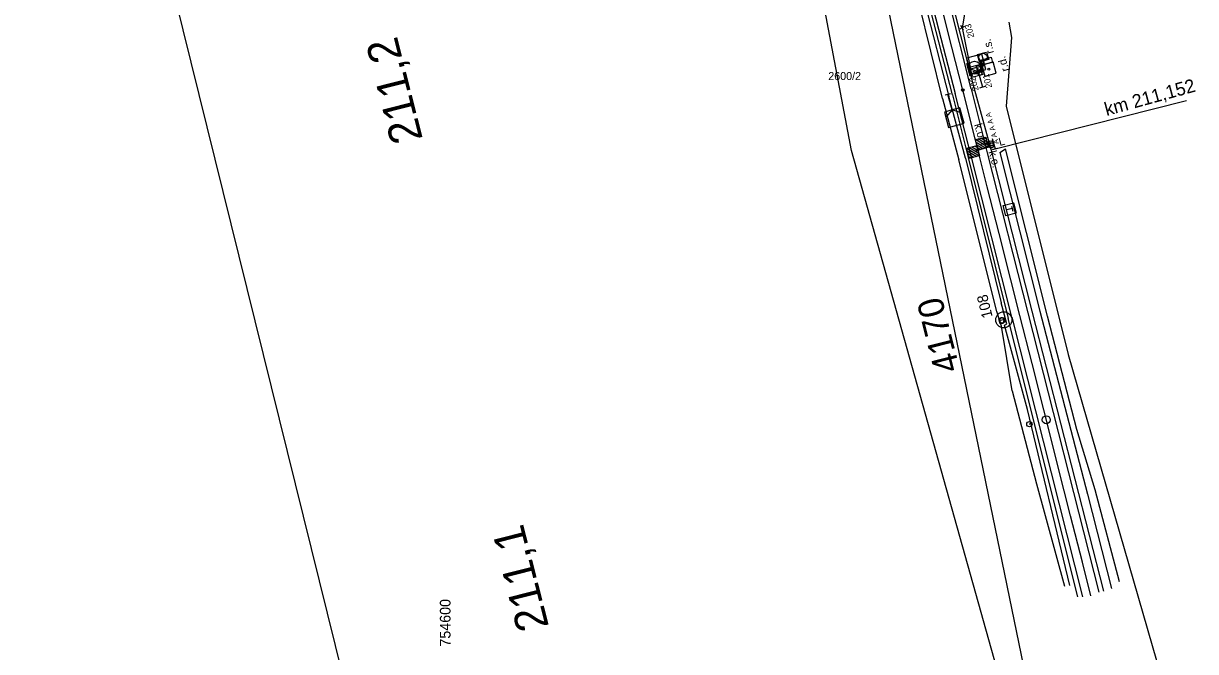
# Model space of a CAD drawing. Extents: x -754679 to -754173, y -1169241 to -1168288.
# Drawn here: x -754679.1 to -754459.3, y -1168596.9 to -1168479.1 of the extents above; entities that cross this region are included whole.
import ezdxf

# ---------------------------------------------------------------- set-up
doc = ezdxf.new("R2010")
doc.units = 0
for name, color, linetype in [('Default', 7, 'Continuous'), ('Vrstva 1', 7, 'Continuous'), ('Vrstva 11', 7, 'Continuous'), ('Vrstva 12', 7, 'Continuous'), ('Vrstva 16', 7, 'Continuous'), ('Vrstva 2', 7, 'Continuous'), ('Vrstva 23', 7, 'Continuous'), ('Vrstva 25', 7, 'Continuous'), ('Vrstva 27', 7, 'Continuous'), ('Vrstva 3', 7, 'Continuous'), ('Vrstva 33', 7, 'Continuous'), ('Vrstva 36', 7, 'Continuous'), ('Vrstva 4', 7, 'Continuous'), ('Vrstva 45', 7, 'Continuous'), ('Vrstva 53', 7, 'Continuous'), ('Vrstva 55', 7, 'Continuous'), ('Vrstva 57', 7, 'Continuous'), ('Vrstva 59', 7, 'Continuous'), ('Vrstva 6', 7, 'Continuous'), ('Vrstva 60', 7, 'Continuous'), ('Vrstva 61', 7, 'Continuous'), ('Vrstva 63', 7, 'Continuous'), ('Vrstva 7', 7, 'Continuous')]:
    doc.layers.add(name, color=color, linetype=linetype)

msp = doc.modelspace()

# ---------------------------------------------------------------- linework, layer by layer
at = {"layer": 'Vrstva 1'}
msp.add_line((-754495.29, -1168534.73), (-754495.29, -1168534.73), dxfattribs=at)
for points in [[(-754498.39, -1168509.75), (-754500.09, -1168503), (-754500.37, -1168501.89), (-754500.59, -1168501.05), (-754502.8, -1168492.33), (-754502.98, -1168491.62), (-754505.01, -1168483.59), (-754507.47, -1168473.86), (-754508.58, -1168469.47), (-754510.81, -1168460.63), (-754513.14, -1168451.47)], [(-754478.97, -1168586.46), (-754480.56, -1168580.17), (-754482.76, -1168571.47), (-754485.13, -1168562.12), (-754486.61, -1168556.26), (-754487.79, -1168551.61), (-754490, -1168542.89), (-754492.27, -1168533.93), (-754493.96, -1168527.25), (-754496.18, -1168518.51), (-754498.39, -1168509.75)]]:
    msp.add_lwpolyline(points, dxfattribs=at)
msp.add_circle((-754502.98, -1168491.62), 0.25, dxfattribs=at)
at = {"layer": 'Vrstva 11'}
for p, q in [((-754496.27, -1168534.44), (-754496.03, -1168535.41)), ((-754495.18, -1168534.68), (-754496.15, -1168534.92)), ((-754495.3, -1168534.19), (-754495.06, -1168535.16))]:
    msp.add_line(p, q, dxfattribs=at)
at = {"layer": 'Vrstva 12'}
for p, q in [((-754496.12, -1168534.91), (-754496.17, -1168534.91)), ((-754495.81, -1168534.34), (-754495.8, -1168534.38)), ((-754495.5, -1168535.26), (-754495.53, -1168535.37)), ((-754495.23, -1168534.71), (-754495.16, -1168534.7))]:
    msp.add_line(p, q, dxfattribs=at)
for centre, major_axis, ratio, start_param, end_param in [((-754495.64, -1168534.85), (0.46, -0.299), 0.939519, 2.440374, 5.467649), ((-754495.66, -1168534.82), (0.313, -0.341), 0.999908, 2.707105, 5.898813), ((-754495.67, -1168534.86), (-0.496, 0.233), 0.95292, 2.24933, 5.396238), ((-754495.68, -1168534.83), (-0.307, 0.348), 0.999899, 2.814721, 5.829233)]:
    msp.add_ellipse(centre, major_axis=major_axis, ratio=ratio, start_param=start_param, end_param=end_param, dxfattribs=at)
at = {"layer": 'Vrstva 16'}
for p, q in [((-754506.81, -1168493.21), (-754511.13, -1168475.45)), ((-754510.13, -1168475.09), (-754505.57, -1168492.82)), ((-754499.42, -1168486.91), (-754500.49, -1168487.18)), ((-754500.49, -1168487.18), (-754500.07, -1168488.86)), ((-754500.07, -1168488.86), (-754498.95, -1168488.59)), ((-754506.81, -1168493.21), (-754503.69, -1168504.74)), ((-754502.48, -1168504.38), (-754505.57, -1168492.82)), ((-754496.02, -1168503.32), (-754494.99, -1168502.63)), ((-754487.09, -1168534.06), (-754494.99, -1168502.63)), ((-754502.48, -1168504.38), (-754495.81, -1168531.52)), ((-754496.02, -1168503.32), (-754488.52, -1168533.07)), ((-754493.73, -1168548.02), (-754495.69, -1168535.92)), ((-754490.87, -1168551.56), (-754495.14, -1168535.72)), ((-754482.94, -1168584.52), (-754490.87, -1168551.56))]:
    msp.add_line(p, q, dxfattribs=at)
for points in [[(-754498.52, -1168484.54), (-754498.07, -1168485.91), (-754499.86, -1168486.34), (-754500.24, -1168484.98), (-754498.52, -1168484.54)], [(-754495.69, -1168535.92), (-754496.62, -1168533.18), (-754503.69, -1168504.74)], [(-754495.14, -1168535.72), (-754494.75, -1168535.49), (-754495.81, -1168531.52)], [(-754488.52, -1168533.07), (-754479.58, -1168567.39), (-754475.12, -1168585.13)], [(-754473.58, -1168583.88), (-754478.14, -1168566.62), (-754481.61, -1168555.3), (-754487.09, -1168534.06)], [(-754493.73, -1168548.02), (-754489.17, -1168565.46), (-754483.92, -1168584.68)]]:
    msp.add_lwpolyline(points, dxfattribs=at)
at = {"layer": 'Vrstva 23'}
for p, q in [((-754499.42, -1168486.91), (-754497.31, -1168486.33)), ((-754496.71, -1168488.44), (-754497.31, -1168486.33)), ((-754498.83, -1168489.01), (-754496.71, -1168488.44))]:
    msp.add_line(p, q, dxfattribs=at)
msp.add_lwpolyline([(-754499.42, -1168486.91), (-754498.95, -1168488.59), (-754498.83, -1168489.01)], dxfattribs=at)
at = {"layer": 'Vrstva 25'}
msp.add_lwpolyline([(-754499.35, -1168486.97), (-754499.61, -1168486.01), (-754497.68, -1168485.49), (-754497.42, -1168486.45), (-754499.35, -1168486.97)], dxfattribs=at)
at = {"layer": 'Vrstva 27'}
for p, q in [((-754497.75, -1168501.6), (-754497.72, -1168501.7)), ((-754497.68, -1168501.94), (-754497.65, -1168502.03))]:
    msp.add_line(p, q, dxfattribs=at)
for points in [[(-754497.67, -1168501.98), (-754497.76, -1168502.04), (-754498.18, -1168502.37), (-754500.59, -1168503.1)], [(-754497.74, -1168501.65), (-754497.85, -1168501.69), (-754498.11, -1168501.53), (-754498.62, -1168501.57), (-754499.53, -1168501.81)]]:
    msp.add_lwpolyline(points, dxfattribs=at)
for centre in [(-754497.74, -1168501.65), (-754497.67, -1168501.98)]:
    msp.add_circle(centre, 0.5, dxfattribs=at)
at = {"layer": 'Vrstva 3'}
for p, q in [((-754502.28, -1168486.6), (-754501.63, -1168488.97)), ((-754501.95, -1168487.78), (-754499.58, -1168487.13)), ((-754499.9, -1168485.94), (-754499.25, -1168488.32)), ((-754502.28, -1168502.51), (-754499.85, -1168503.97)), ((-754501.76, -1168502.38), (-754499.98, -1168503.46)), ((-754501.25, -1168502.26), (-754500.11, -1168502.94)), ((-754500.73, -1168502.13), (-754500.24, -1168502.43)), ((-754498.19, -1168502.39), (-754500.61, -1168500.92)), ((-754498.71, -1168502.52), (-754500.48, -1168501.44)), ((-754499.22, -1168502.64), (-754500.36, -1168501.95)), ((-754499.74, -1168502.77), (-754500.23, -1168502.47)), ((-754498.32, -1168501.88), (-754500.09, -1168500.8)), ((-754498.44, -1168501.36), (-754499.58, -1168500.67)), ((-754498.57, -1168500.84), (-754499.06, -1168500.54)), ((-754502.15, -1168503.03), (-754500.37, -1168504.1)), ((-754502.02, -1168503.54), (-754500.88, -1168504.23)), ((-754501.89, -1168504.06), (-754501.4, -1168504.35))]:
    msp.add_line(p, q, dxfattribs=at)
for points in [[(-754500.14, -1168502.86), (-754500.61, -1168500.92), (-754498.67, -1168500.45), (-754498.19, -1168502.39)], [(-754500.34, -1168502.03), (-754499.85, -1168503.97), (-754501.79, -1168504.45), (-754502.28, -1168502.51)]]:
    msp.add_lwpolyline(points, close=True, dxfattribs=at)
msp.add_circle((-754500.76, -1168487.45), 1.23, dxfattribs=at)
at = {"layer": 'Vrstva 33'}
for p, q in [((-754500.1, -1168487.94), (-754501.07, -1168488.19)), ((-754500.23, -1168487.45), (-754499.97, -1168488.42)), ((-754493.84, -1168513.39), (-754493.6, -1168514.36)), ((-754493.72, -1168513.87), (-754494.69, -1168514.11))]:
    msp.add_line(p, q, dxfattribs=at)
for points in [[(-754499.87, -1168486.84), (-754499.36, -1168488.78), (-754501.3, -1168489.28), (-754501.8, -1168487.35), (-754499.87, -1168486.84)], [(-754493.47, -1168512.78), (-754492.99, -1168514.72), (-754494.93, -1168515.2), (-754495.42, -1168513.26), (-754493.47, -1168512.78)]]:
    msp.add_lwpolyline(points, dxfattribs=at)
at = {"layer": 'Vrstva 36'}
msp.add_line((-754499.19, -1168486.22), (-754499.19, -1168487.22), dxfattribs=at)
msp.add_circle((-754499.19, -1168485.47), 0.757, dxfattribs=at)
at = {"layer": 'Vrstva 4'}
for p, q in [((-754501.4, -1168491.43), (-754506.85, -1168469.86)), ((-754500.85, -1168491.23), (-754505.96, -1168471.15)), ((-754504.93, -1168492.55), (-754509.45, -1168474.86)), ((-754508.88, -1168474.9), (-754504.39, -1168492.29)), ((-754501.4, -1168491.43), (-754498.34, -1168503.66)), ((-754497.49, -1168503.47), (-754500.85, -1168491.23)), ((-754504.93, -1168492.55), (-754501.99, -1168504.3)), ((-754501.32, -1168504.2), (-754504.39, -1168492.29)), ((-754501.99, -1168504.3), (-754494.47, -1168534.44)), ((-754493.78, -1168534.21), (-754501.32, -1168504.2)), ((-754498.34, -1168503.66), (-754490.79, -1168533.41)), ((-754490, -1168533.07), (-754497.49, -1168503.47)), ((-754490.79, -1168533.41), (-754477.47, -1168585.79)), ((-754476.54, -1168585.62), (-754490, -1168533.07)), ((-754481.4, -1168586.69), (-754494.47, -1168534.44)), ((-754493.78, -1168534.21), (-754480.52, -1168586.64))]:
    msp.add_line(p, q, dxfattribs=at)
at = {"layer": 'Vrstva 45'}
msp.add_lwpolyline([(-754503.77, -1168472.48), (-754502.62, -1168477.03), (-754503.11, -1168479.94), (-754501.32, -1168488.67), (-754499.51, -1168488.21)], dxfattribs=at)
at = {"layer": 'Vrstva 53'}
for p, q in [((-754523.85, -1168502.96), (-754531.99, -1168459.75)), ((-754494.32, -1168478.89), (-754493.82, -1168481.8)), ((-754493.82, -1168481.8), (-754494.84, -1168494.63)), ((-754494.84, -1168494.63), (-754483.21, -1168541.23)), ((-754490.14, -1168623.07), (-754523.85, -1168502.96)), ((-754483.21, -1168541.23), (-754460.6, -1168619.67))]:
    msp.add_line(p, q, dxfattribs=at)
at = {"layer": 'Vrstva 55'}
msp.add_line((-754486.32, -1168624.94), (-754519.8, -1168462.41), dxfattribs=at)
at = {"layer": 'Vrstva 59'}
msp.add_circle((-754498.09, -1168487.73), 0.175, dxfattribs=at)
at = {"layer": 'Vrstva 6'}
for p, q in [((-754502.68, -1168479.69), (-754503.54, -1168480.19)), ((-754502.86, -1168480.37), (-754503.36, -1168479.51)), ((-754500.89, -1168488.42), (-754501.75, -1168488.92)), ((-754501.07, -1168489.1), (-754501.57, -1168488.24)), ((-754499.08, -1168487.96), (-754499.94, -1168488.46)), ((-754499.26, -1168488.64), (-754499.76, -1168487.78)), ((-754496.93, -1168502.65), (-754461.01, -1168493.56)), ((-754497.46, -1168500.74), (-754496.93, -1168502.65)), ((-754497.42, -1168502.78), (-754496.45, -1168502.52))]:
    msp.add_line(p, q, dxfattribs=at)
at = {"layer": 'Vrstva 61'}
msp.add_line((-754679.07, -1168359.54), (-754578.24, -1168767.26), dxfattribs=at)
at = {"layer": 'Vrstva 63'}
msp.add_line((-754495.39, -1168534.73), (-754495.19, -1168534.73), dxfattribs=at)
msp.add_circle((-754495.29, -1168534.73), 1.51, dxfattribs=at)
at = {"layer": 'Vrstva 7'}
for p, q in [((-754500.07, -1168488.17), (-754499.28, -1168491.06)), ((-754499.76, -1168491.2), (-754498.79, -1168490.93)), ((-754505.3, -1168492.32), (-754506.26, -1168492.59)), ((-754504.98, -1168495.35), (-754505.78, -1168492.46)), ((-754490.43, -1168554.26), (-754490.53, -1168554.29))]:
    msp.add_line(p, q, dxfattribs=at)
for points in [[(-754500.07, -1168488.17), (-754498.63, -1168487.77), (-754499.42, -1168484.88), (-754502.31, -1168485.68), (-754501.52, -1168488.57), (-754500.07, -1168488.17)], [(-754501.78, -1168487.6), (-754500.07, -1168488.17), (-754498.89, -1168486.81)], [(-754504.98, -1168495.35), (-754506.43, -1168495.75), (-754505.63, -1168498.64), (-754502.74, -1168497.84), (-754503.54, -1168494.95), (-754504.98, -1168495.35)], [(-754503.27, -1168495.92), (-754504.98, -1168495.35), (-754506.16, -1168496.71)]]:
    msp.add_lwpolyline(points, dxfattribs=at)
for centre, radius in [((-754487.32, -1168553.47), 0.75), ((-754490.48, -1168554.28), 0.5)]:
    msp.add_circle(centre, radius, dxfattribs=at)

# ---------------------------------------------------------------- texts
at = {"layer": 'Default'}
msp.add_text('754600', height=2, rotation=90, dxfattribs=at).set_placement((-754599, -1168596))
at = {"layer": 'Vrstva 11'}
msp.add_text('108', height=2, rotation=104.1769, dxfattribs=at).set_placement((-754497.35, -1168534.13))
at = {"layer": 'Vrstva 2'}
msp.add_text('4170', height=4.8, rotation=104.1384, dxfattribs=at).set_placement((-754503.5, -1168543.99))
at = {"layer": 'Vrstva 23'}
msp.add_text('r.d.', height=1.5, rotation=105.7615, dxfattribs=at).set_placement((-754494.28, -1168487.93))
at = {"layer": 'Vrstva 25'}
msp.add_text('r.s.', height=1.5, rotation=104.2177, dxfattribs=at).set_placement((-754497.1, -1168484.62))
at = {"layer": 'Vrstva 27'}
for p in [(-754500.86, -1168498.12), (-754498.17, -1168503.22)]:
    msp.add_text('k.o.', height=1.5, rotation=285.3513, dxfattribs=at).set_placement(p)
at = {"layer": 'Vrstva 57'}
msp.add_text('2600/2', height=1.5, dxfattribs=at).set_placement((-754528.19, -1168489.75))
at = {"layer": 'Vrstva 6'}
for s, height, rotation, p in [('km 211,152', 2.5, 15.3838, (-754476.02, -1168496.5)), ('  A A A A A ', 1, 105.3838, (-754495.97, -1168502.39)), ('L', 1.5, 14.1581, (-754496.04, -1168502.12))]:
    msp.add_text(s, height=height, rotation=rotation, dxfattribs=at).set_placement(p)
at = {"layer": 'Vrstva 60'}
for s, p in [('203', (-754500.8, -1168481.7)), ('202', (-754499.96, -1168491.62)), ('201', (-754497.45, -1168491.09))]:
    msp.add_text(s, height=1.2, rotation=105, dxfattribs=at).set_placement(p)
at = {"layer": 'Vrstva 7'}
for s, rotation, p in [('211,2', 104.1773, (-754604.18, -1168500.8)), ('211,1', 104.2188, (-754580.53, -1168592.24))]:
    msp.add_text(s, height=6, rotation=rotation, dxfattribs=at).set_placement(p)

doc.saveas('drawing.dxf')
